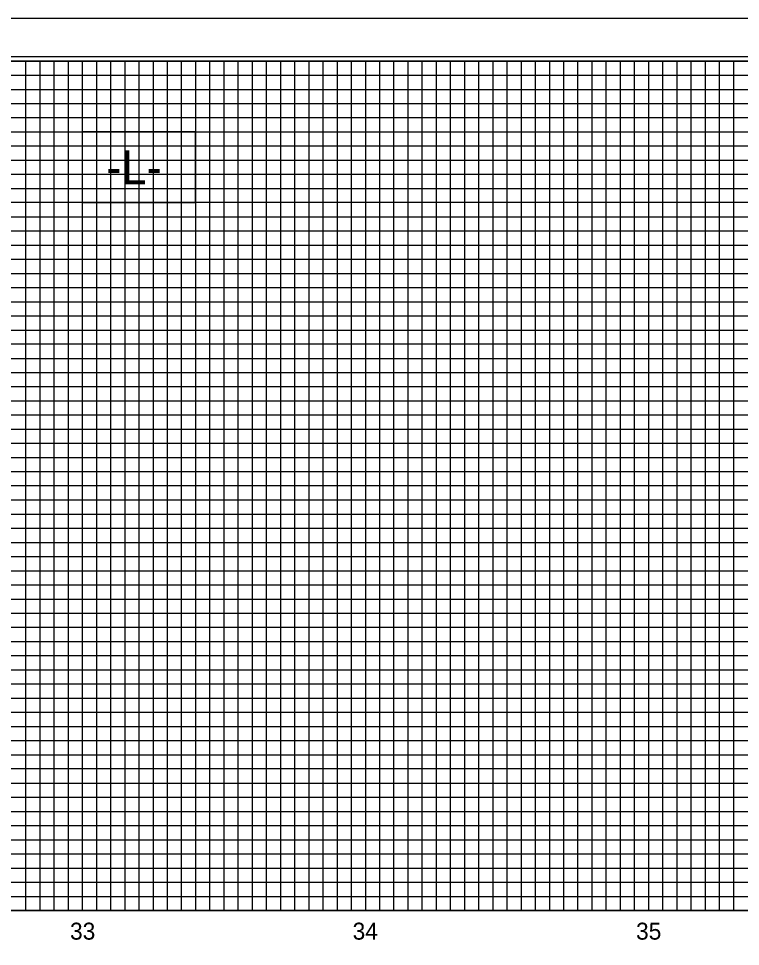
# Model space of a CAD drawing. Extents: x 2113763 to 2114783, y 714280 to 714940.
# Drawn here: x 2114270.3 to 2114525.3, y 714612.6 to 714940.3 of the extents above; entities that cross this region are included whole.
import ezdxf

# ---------------------------------------------------------------- set-up
doc = ezdxf.new("R2010")
doc.units = 0
for name, color, linetype in [('Exist Vertical Profile Horizontal Axis Label Major', 7, 'Continuous'), ('Prop Grid Mask', 7, 'Continuous'), ('Prop PFL Text', 7, 'Continuous'), ('Sheet Cutting Line CELL', 7, 'Continuous'), ('Sheet Layout Profile Border Port 1', 7, 'Continuous'), ('Sheet Plot Border Inside CELL', 7, 'Continuous'), ('Sheet Plot Border Outside CELL', 7, 'Continuous'), ('Sheet Profile CELL', 7, 'Continuous'), ('Sheet Profile Grid Major CELL', 7, 'Continuous'), ('Sheet Profile Grid Middle CELL', 7, 'Continuous'), ('Sheet Profile Grid Minor CELL', 7, 'Continuous')]:
    doc.layers.add(name, color=color, linetype=linetype)

msp = doc.modelspace()

# ---------------------------------------------------------------- linework, layer by layer
at = {"layer": 'Prop Grid Mask'}
msp.add_lwpolyline([(2114292.76, 714875.29), (2114332.76, 714875.29), (2114332.76, 714900.29), (2114292.76, 714900.29)], close=True, dxfattribs=at)
at = {"layer": 'Prop PFL Text'}
msp.add_lwpolyline([(2114292.76, 714875.29), (2114332.76, 714875.29), (2114332.76, 714900.29), (2114292.76, 714900.29)], close=True, dxfattribs=at)
at = {"layer": 'Sheet Cutting Line CELL'}
msp.add_line((2114782.56, 714940.29), (2113762.56, 714940.29), dxfattribs=at)
at = {"layer": 'Sheet Layout Profile Border Port 1'}
msp.add_lwpolyline([(2113892.76, 714925.29), (2114642.73, 714925.29), (2114642.73, 714805.41), (2114732.76, 714805.29), (2114732.76, 714625.29), (2113892.76, 714625.29)], close=True, dxfattribs=at)
at = {"layer": 'Sheet Plot Border Inside CELL'}
msp.add_lwpolyline([(2113770.36, 714293.76), (2114770.26, 714293.76), (2114770.26, 714926.82), (2113770.36, 714926.82)], close=True, dxfattribs=at)
at = {"layer": 'Sheet Plot Border Outside CELL'}
msp.add_lwpolyline([(2113762.56, 714280.29), (2114782.56, 714280.29), (2114782.56, 714940.29), (2113762.56, 714940.29)], close=True, dxfattribs=at)
at = {"layer": 'Sheet Profile CELL'}
msp.add_line((2113862.76, 714625.29), (2114762.76, 714625.29), dxfattribs=at)
msp.add_lwpolyline([(2114762.76, 714925.29), (2113862.76, 714925.29), (2113862.76, 714295.29), (2114762.76, 714295.29)], close=True, dxfattribs=at)
at = {"layer": 'Sheet Profile Grid Major CELL'}
for p, q in [((2114292.76, 714925.29), (2114292.76, 714625.29)), ((2114317.76, 714925.29), (2114317.76, 714625.29)), ((2114342.76, 714925.29), (2114342.76, 714625.29)), ((2114367.76, 714925.29), (2114367.76, 714625.29)), ((2114392.76, 714925.29), (2114392.76, 714625.29)), ((2114417.76, 714925.29), (2114417.76, 714625.29)), ((2114442.76, 714925.29), (2114442.76, 714625.29)), ((2114467.76, 714925.29), (2114467.76, 714625.29)), ((2114492.76, 714925.29), (2114492.76, 714625.29)), ((2114517.76, 714925.29), (2114517.76, 714625.29)), ((2113862.76, 714900.29), (2114642.76, 714900.29)), ((2114642.76, 714875.29), (2113862.76, 714875.29)), ((2113862.76, 714850.29), (2114642.76, 714850.29)), ((2114642.76, 714825.29), (2113862.76, 714825.29)), ((2113862.76, 714800.29), (2114762.76, 714800.29)), ((2114762.76, 714775.29), (2113862.76, 714775.29)), ((2113862.76, 714750.29), (2114762.76, 714750.29)), ((2114762.76, 714725.29), (2113862.76, 714725.29)), ((2113862.76, 714700.29), (2114762.76, 714700.29)), ((2114762.76, 714675.29), (2113862.76, 714675.29)), ((2113862.76, 714650.29), (2114762.76, 714650.29))]:
    msp.add_line(p, q, dxfattribs=at)
at = {"layer": 'Sheet Profile Grid Middle CELL'}
for p, q in [((2113892.76, 714920.29), (2114642.76, 714920.29)), ((2113892.76, 714915.29), (2114642.76, 714915.29)), ((2113892.76, 714910.29), (2114642.76, 714910.29)), ((2113892.76, 714905.29), (2114642.76, 714905.29)), ((2113892.76, 714895.29), (2114642.76, 714895.29)), ((2113892.76, 714890.29), (2114642.76, 714890.29)), ((2113892.76, 714885.29), (2114642.76, 714885.29)), ((2113892.76, 714880.29), (2114642.76, 714880.29)), ((2113892.76, 714870.29), (2114642.76, 714870.29)), ((2113892.76, 714865.29), (2114642.76, 714865.29)), ((2113892.76, 714860.29), (2114642.76, 714860.29)), ((2113892.76, 714855.29), (2114642.76, 714855.29)), ((2113892.76, 714845.29), (2114642.76, 714845.29)), ((2113892.76, 714840.29), (2114642.76, 714840.29)), ((2113892.76, 714835.29), (2114642.76, 714835.29)), ((2113892.76, 714830.29), (2114642.76, 714830.29)), ((2113892.76, 714820.29), (2114642.76, 714820.29)), ((2113892.76, 714815.29), (2114642.76, 714815.29)), ((2113892.76, 714810.29), (2114642.76, 714810.29)), ((2113892.76, 714805.29), (2114732.76, 714805.29)), ((2113892.76, 714795.29), (2114732.76, 714795.29)), ((2113892.76, 714790.29), (2114732.76, 714790.29)), ((2113892.76, 714785.29), (2114732.76, 714785.29)), ((2113892.76, 714780.29), (2114732.76, 714780.29)), ((2113892.76, 714770.29), (2114732.76, 714770.29)), ((2113892.76, 714765.29), (2114732.76, 714765.29)), ((2113892.76, 714760.29), (2114732.76, 714760.29)), ((2113892.76, 714755.29), (2114732.76, 714755.29)), ((2113892.76, 714745.29), (2114732.76, 714745.29)), ((2113892.76, 714740.29), (2114732.76, 714740.29)), ((2113892.76, 714735.29), (2114732.76, 714735.29)), ((2113892.76, 714730.29), (2114732.76, 714730.29)), ((2113892.76, 714720.29), (2114732.76, 714720.29)), ((2113892.76, 714715.29), (2114732.76, 714715.29)), ((2113892.76, 714710.29), (2114732.76, 714710.29)), ((2113892.76, 714705.29), (2114732.76, 714705.29)), ((2113892.76, 714695.29), (2114732.76, 714695.29)), ((2113892.76, 714690.29), (2114732.76, 714690.29)), ((2113892.76, 714685.29), (2114732.76, 714685.29)), ((2113892.76, 714680.29), (2114732.76, 714680.29)), ((2113892.76, 714670.29), (2114732.76, 714670.29)), ((2113892.76, 714665.29), (2114732.76, 714665.29)), ((2113892.76, 714660.29), (2114732.76, 714660.29)), ((2113892.76, 714655.29), (2114732.76, 714655.29)), ((2113892.76, 714645.29), (2114732.76, 714645.29)), ((2113892.76, 714640.29), (2114732.76, 714640.29)), ((2113892.76, 714635.29), (2114732.76, 714635.29)), ((2113892.76, 714630.29), (2114732.76, 714630.29))]:
    msp.add_line(p, q, dxfattribs=at)
at = {"layer": 'Sheet Profile Grid Minor CELL'}
for p, q in [((2114272.76, 714925.29), (2114272.76, 714625.29)), ((2114277.76, 714925.29), (2114277.76, 714625.29)), ((2114282.76, 714925.29), (2114282.76, 714625.29)), ((2114287.76, 714925.29), (2114287.76, 714625.29)), ((2114297.76, 714925.29), (2114297.76, 714625.29)), ((2114302.76, 714925.29), (2114302.76, 714625.29)), ((2114307.76, 714925.29), (2114307.76, 714625.29)), ((2114312.76, 714925.29), (2114312.76, 714625.29)), ((2114322.76, 714925.29), (2114322.76, 714625.29)), ((2114327.76, 714925.29), (2114327.76, 714625.29)), ((2114332.76, 714925.29), (2114332.76, 714625.29)), ((2114337.76, 714925.29), (2114337.76, 714625.29)), ((2114347.76, 714925.29), (2114347.76, 714625.29)), ((2114352.76, 714925.29), (2114352.76, 714625.29)), ((2114357.76, 714925.29), (2114357.76, 714625.29)), ((2114362.76, 714925.29), (2114362.76, 714625.29)), ((2114372.76, 714925.29), (2114372.76, 714625.29)), ((2114377.76, 714925.29), (2114377.76, 714625.29)), ((2114382.76, 714925.29), (2114382.76, 714625.29)), ((2114387.76, 714925.29), (2114387.76, 714625.29)), ((2114397.76, 714925.29), (2114397.76, 714625.29)), ((2114402.76, 714925.29), (2114402.76, 714625.29)), ((2114407.76, 714925.29), (2114407.76, 714625.29)), ((2114412.76, 714925.29), (2114412.76, 714625.29)), ((2114422.76, 714925.29), (2114422.76, 714625.29)), ((2114427.76, 714925.29), (2114427.76, 714625.29)), ((2114432.76, 714925.29), (2114432.76, 714625.29)), ((2114437.76, 714925.29), (2114437.76, 714625.29)), ((2114447.76, 714925.29), (2114447.76, 714625.29)), ((2114452.76, 714925.29), (2114452.76, 714625.29)), ((2114457.76, 714925.29), (2114457.76, 714625.29)), ((2114462.76, 714925.29), (2114462.76, 714625.29)), ((2114472.76, 714925.29), (2114472.76, 714625.29)), ((2114477.76, 714925.29), (2114477.76, 714625.29)), ((2114482.76, 714925.29), (2114482.76, 714625.29)), ((2114487.76, 714925.29), (2114487.76, 714625.29)), ((2114497.76, 714925.29), (2114497.76, 714625.29)), ((2114502.76, 714925.29), (2114502.76, 714625.29)), ((2114507.76, 714925.29), (2114507.76, 714625.29)), ((2114512.76, 714925.29), (2114512.76, 714625.29)), ((2114522.76, 714925.29), (2114522.76, 714625.29))]:
    msp.add_line(p, q, dxfattribs=at)

# ---------------------------------------------------------------- texts
at = {"layer": 'Exist Vertical Profile Horizontal Axis Label Major'}
for s, p in [('33', (2114288.45, 714615)), ('33', (2114288.45, 714615)), ('33', (2114288.45, 714615)), ('33', (2114288.45, 714615)), ('34', (2114388.27, 714615)), ('34', (2114388.27, 714615)), ('34', (2114388.27, 714615)), ('34', (2114388.27, 714615)), ('35', (2114488.39, 714615)), ('35', (2114488.39, 714615)), ('35', (2114488.39, 714615)), ('35', (2114488.39, 714615)), ('35', (2114488.39, 714615)), ('35', (2114488.39, 714615))]:
    msp.add_text(s, height=6, dxfattribs=at).set_placement(p)
at = {"layer": 'Prop PFL Text'}
msp.add_text('-L-', height=12, dxfattribs=at).set_placement((2114301.22, 714881.79))

doc.saveas('drawing.dxf')
